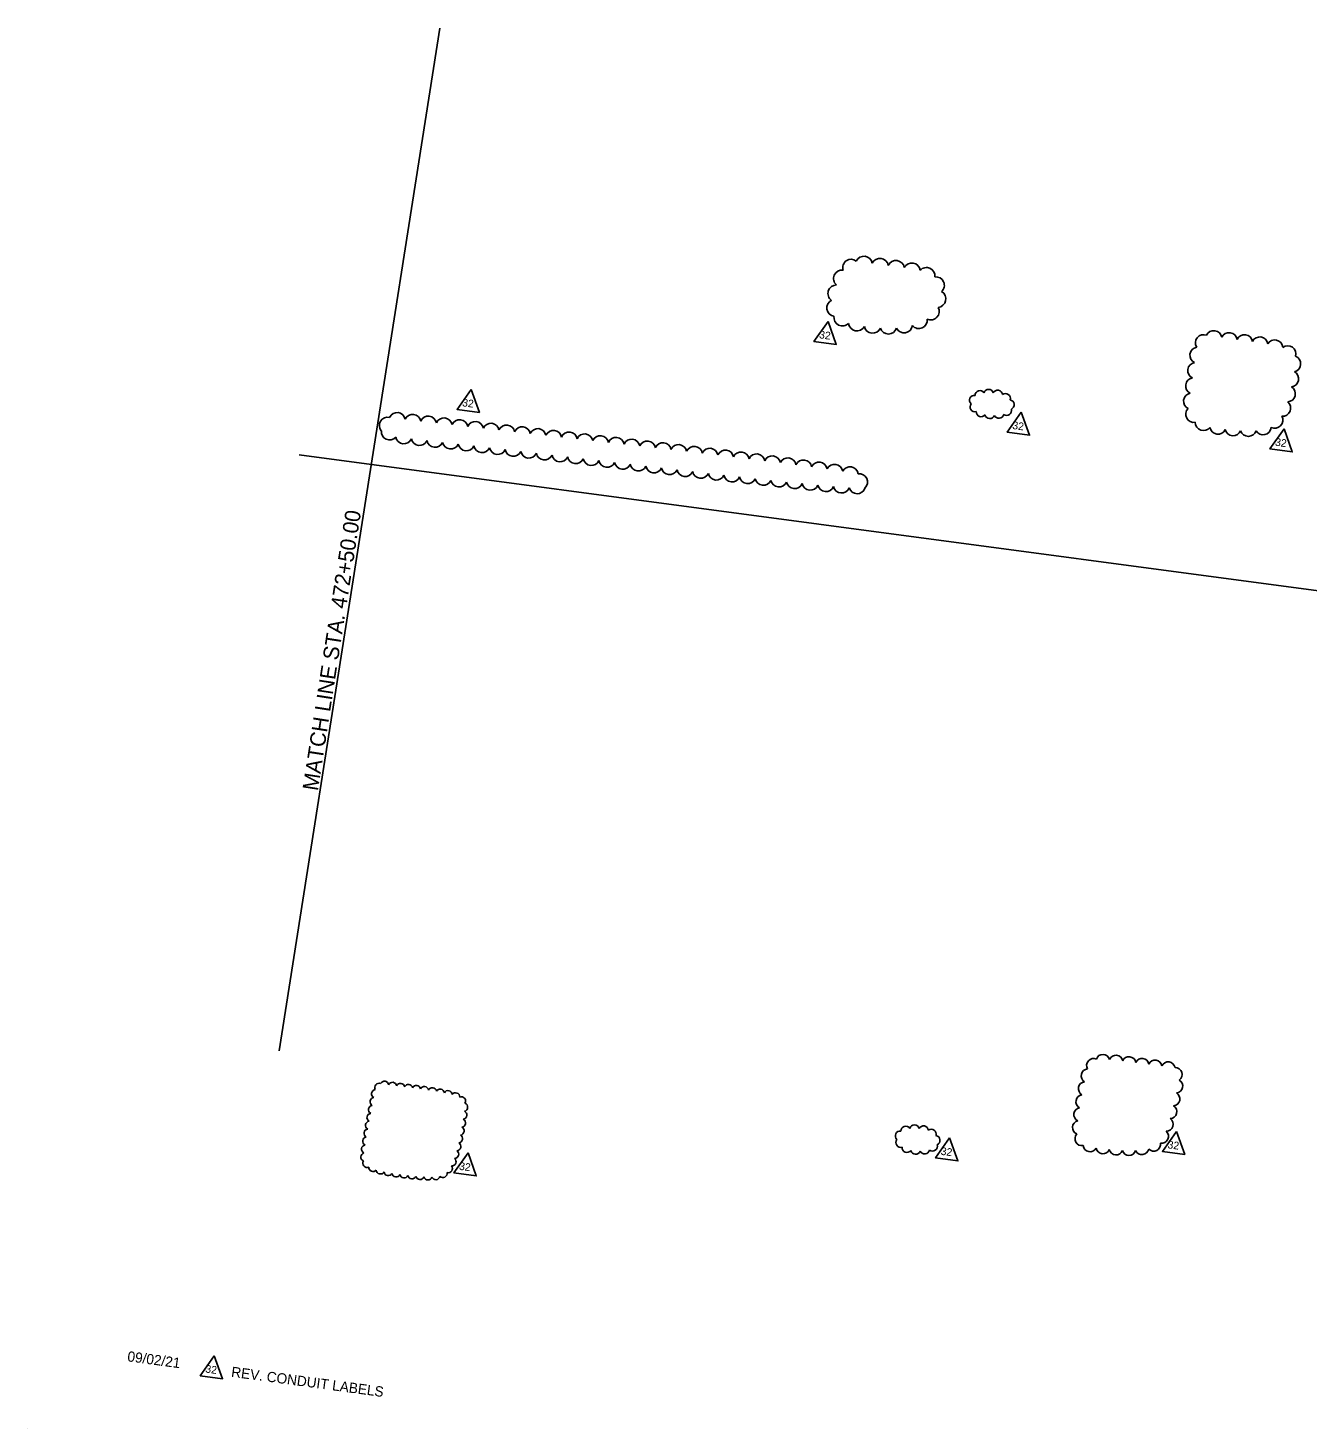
# Model space of a CAD drawing. Extents: x 925493 to 926837, y 636307 to 637171.
# Drawn here: x 925493 to 926150, y 636452 to 637171 of the extents above; entities that cross this region are included whole.
import ezdxf

# ---------------------------------------------------------------- set-up
doc = ezdxf.new("R2010")
doc.units = 0
for name, color, linetype in [('ActivePointCell_dp', 7, 'Continuous'), ('AdhocPoint_dp', 7, 'Continuous'), ('Cloud_dp', 7, 'Continuous'), ('MatchLines_dp', 7, 'Continuous'), ('TextLabel', 7, 'Continuous'), ('TextNotes', 7, 'Continuous')]:
    doc.layers.add(name, color=color, linetype=linetype)

msp = doc.modelspace()

# ---------------------------------------------------------------- linework, layer by layer
at = {"layer": 'ActivePointCell_dp'}
msp.add_line((926709.43, 636807.88), (925632.34, 636951.66), dxfattribs=at)
at = {"layer": 'AdhocPoint_dp'}
msp.add_line((925493.14, 636452.35), (925493.14, 636452.35), dxfattribs=at)
at = {"layer": 'Cloud_dp'}
for points in [[(925903.7, 637020.16), (925896.5, 637009.89), (925907.95, 637008.36)], [(925720.53, 636985.27), (925713.33, 636975.01), (925724.78, 636973.48)], [(926002.88, 636973.59), (925995.68, 636963.33), (926007.13, 636961.8)], [(926137.71, 636965), (926130.51, 636954.74), (926141.96, 636953.21)], [(925966.12, 636601.18), (925958.92, 636590.92), (925970.38, 636589.39)], [(926082.55, 636604.53), (926075.35, 636594.26), (926086.81, 636592.74)], [(925718.95, 636593.49), (925711.75, 636583.23), (925723.2, 636581.7)]]:
    msp.add_lwpolyline(points, close=True, dxfattribs=at)
for centre, radius, start, end in [((925915.56, 637047.7), 4.34, 52.01002, 197.01002), ((925922.15, 637049.28), 4.34, 9.89674, 154.89674), ((925930.36, 637048.19), 4.34, 9.89674, 154.89674), ((925938.56, 637047.09), 4.34, 9.80382, 154.80382), ((925910.88, 637042.13), 4.34, 83.06239, 228.06239), ((925946.68, 637045.82), 4.34, 7.52021, 152.52021), ((925954.22, 637043.5), 4.34, 353.21175, 138.21175), ((925908.01, 637034.56), 4.34, 90.39209, 235.39209), ((925959.07, 637038.68), 4.34, 312.15567, 97.15567), ((925907.45, 637027.09), 4.34, 116.00337, 261.00337), ((925959.83, 637031.7), 4.34, 275.24637, 60.24637), ((925911.06, 637022.17), 4.34, 171.5858, 316.5858), ((925956.45, 637025.24), 4.34, 244.59572, 29.59572), ((925918.53, 637019.67), 4.34, 186.41343, 331.41343), ((925926.59, 637018.47), 4.34, 191.6571, 336.6571), ((925934.72, 637018.02), 4.34, 196.9198, 341.9198), ((925942.72, 637018.62), 4.34, 206.67781, 351.67781), ((925950.28, 637020.85), 4.34, 221.20066, 6.20066), ((926101.69, 637011.29), 4.16, 9.89674, 154.89674), ((926109.56, 637010.24), 4.16, 9.89674, 154.89674), ((926096.37, 637009.19), 4.16, 68.20431, 213.20431), ((926117.43, 637009.19), 4.16, 9.89674, 154.89674), ((926125.26, 637008.07), 4.16, 8.77387, 153.77387), ((926132.95, 637006.57), 4.16, 4.20701, 149.20701), ((926139.62, 637003.56), 4.16, 342.21927, 127.21927), ((926093.58, 637002.81), 4.16, 99.5249, 244.5249), ((926142.07, 636998.41), 4.16, 283.66055, 68.66055), ((926092.48, 636994.95), 4.16, 99.54688, 244.54688), ((926141.07, 636990.71), 4.16, 276.46775, 61.46775), ((926091.39, 636987.09), 4.16, 99.62003, 244.62003), ((926139.37, 636983.03), 4.16, 273.58469, 58.58469), ((925978.82, 636979.74), 2.51, 82.67056, 227.67056), ((925981.65, 636982.19), 2.51, 34.10765, 179.10765), ((925986.12, 636982.81), 2.51, 16.71694, 161.71694), ((925990.75, 636982.35), 2.51, 6.96113, 151.96113), ((925994.79, 636980.67), 2.51, 342.91745, 127.91745), ((925996.74, 636977.46), 2.51, 294.76198, 79.76198), ((926090.31, 636979.22), 4.16, 99.75917, 244.75917), ((926136.95, 636975.68), 4.16, 264.96518, 49.96518), ((925682.55, 636969.18), 4.23, 10.80208, 155.80208), ((925690.58, 636968.25), 4.23, 10.95178, 155.95178), ((925698.6, 636967.33), 4.23, 10.98257, 155.98257), ((925979.09, 636976.31), 2.51, 141.30835, 286.30835), ((925982.3, 636973.75), 2.51, 176.73132, 321.73132), ((925986.71, 636972.83), 2.51, 194.62704, 339.62704), ((925991.37, 636972.97), 2.52, 203.8708, 348.8708), ((925995.39, 636974.46), 2.51, 231.69605, 16.69605), ((926091.46, 636972.5), 4.16, 134.77757, 279.77757), ((926132.95, 636969.5), 4.16, 244.31058, 29.31058), ((925677.66, 636966.81), 4.23, 75.9759, 220.9759), ((925706.62, 636966.42), 4.23, 10.9986, 155.9986), ((925714.65, 636965.5), 4.23, 11.00888, 156.00888), ((925722.67, 636964.59), 4.23, 11.01618, 156.01618), ((925730.7, 636963.68), 4.23, 11.02173, 156.02173), ((925738.72, 636962.77), 4.23, 11.02612, 156.02612), ((925746.75, 636961.86), 4.23, 11.02971, 156.02971), ((925754.77, 636960.95), 4.23, 11.03272, 156.03272), ((925762.79, 636960.04), 4.23, 11.03528, 156.03528), ((926096.33, 636968.28), 4.16, 178.33859, 323.33859), ((926103.78, 636966.48), 4.16, 189.46094, 334.46094), ((926111.59, 636965.62), 4.16, 192.99146, 337.99146), ((926127.01, 636966.14), 4.16, 209.59075, 354.59075), ((925678.68, 636963.56), 4.23, 173.62719, 318.62719), ((925686, 636961.6), 4.23, 191.40074, 336.40074), ((925694.04, 636960.73), 4.23, 191.17285, 336.17285), ((925702.06, 636959.83), 4.23, 191.05511, 336.05511), ((925710.09, 636958.92), 4.23, 190.97993, 335.97993), ((925718.11, 636958), 4.23, 190.92656, 335.92656), ((925770.82, 636959.13), 4.23, 11.03751, 156.03751), ((925778.84, 636958.22), 4.23, 11.03946, 156.03946), ((925786.87, 636957.31), 4.23, 11.04119, 156.04119), ((925794.89, 636956.4), 4.23, 11.04274, 156.04274), ((925802.92, 636955.49), 4.23, 11.04408, 156.04408), ((925810.94, 636954.58), 4.23, 11.01548, 156.01548), ((925818.96, 636953.67), 4.23, 10.95791, 155.95791), ((925826.98, 636952.74), 4.23, 10.89381, 155.89381), ((926119.41, 636965.33), 4.16, 197.6746, 342.6746), ((925726.14, 636957.07), 4.23, 190.88612, 335.88612), ((925734.16, 636956.14), 4.23, 190.85412, 335.85412), ((925742.18, 636955.2), 4.23, 190.82797, 335.82797), ((925750.2, 636954.26), 4.23, 190.80609, 335.80609), ((925758.22, 636953.32), 4.23, 190.78741, 335.78741), ((925766.24, 636952.37), 4.23, 190.77124, 335.77124), ((925774.26, 636951.42), 4.23, 190.75705, 335.75705), ((925835, 636951.81), 4.23, 10.82186, 155.82186), ((925843.02, 636950.87), 4.23, 10.74032, 155.74032), ((925851.04, 636949.91), 4.23, 10.64682, 155.64682), ((925859.05, 636948.94), 4.23, 10.53815, 155.53815), ((925867.07, 636947.95), 4.23, 10.40969, 155.40969), ((925875.07, 636946.94), 4.23, 10.25458, 155.25458), ((925883.08, 636945.91), 4.23, 10.0621, 155.0621), ((925782.28, 636950.48), 4.23, 190.74447, 335.74447), ((925790.3, 636949.52), 4.23, 190.73477, 335.73477), ((925798.32, 636948.57), 4.23, 190.7552, 335.7552), ((925806.34, 636947.63), 4.23, 190.78932, 335.78932), ((925814.36, 636946.69), 4.23, 190.82718, 335.82718), ((925822.38, 636945.75), 4.23, 190.86951, 335.86951), ((925830.4, 636944.82), 4.23, 190.91729, 335.91729), ((925838.43, 636943.9), 4.23, 190.97179, 335.97179), ((925891.08, 636944.85), 4.23, 9.81432, 154.81432), ((925899.07, 636943.75), 4.23, 9.47827, 154.47827), ((925907.05, 636942.59), 4.23, 8.98444, 153.98444), ((925915.01, 636941.34), 4.23, 8.14869, 153.14869), ((925846.45, 636942.99), 4.23, 191.03473, 336.03473), ((925854.47, 636942.08), 4.23, 191.10857, 336.10857), ((925862.5, 636941.19), 4.23, 191.19687, 336.19687), ((925870.52, 636940.31), 4.23, 191.30506, 336.30506), ((925878.55, 636939.45), 4.23, 191.44197, 336.44197), ((925886.58, 636938.61), 4.23, 191.62312, 336.62312), ((925894.6, 636937.8), 4.23, 191.87914, 336.87914), ((925902.64, 636937.04), 4.23, 192.28253, 337.28253), ((925910.67, 636936.36), 4.23, 193.07403, 338.07403), ((925919.79, 636937.76), 4.22, 313.01562, 98.01562), ((925918.65, 636936), 4.24, 196.68432, 341.68432), ((926039.96, 636638.4), 3.55, 65.89656, 210.89656), ((926044.78, 636640.51), 3.55, 16.33707, 161.33707), ((926051.45, 636640.11), 3.55, 11.8731, 156.8731), ((926058.15, 636639.35), 3.55, 10.18551, 155.18551), ((926064.85, 636638.47), 3.55, 9.89674, 154.89674), ((926071.57, 636637.58), 3.55, 9.89674, 154.89674), ((926037.16, 636633.04), 3.55, 93.9727, 238.9727), ((926078.28, 636636.68), 3.55, 9.89674, 154.89674), ((926081.85, 636633.74), 3.55, 306.25893, 91.25893), ((925673.24, 636627.09), 2.16, 65.85108, 210.85108), ((925676.08, 636628.14), 2.16, 9.89674, 154.89674), ((925680.18, 636627.6), 2.16, 9.89674, 154.89674), ((925684.27, 636627.05), 2.16, 9.89674, 154.89674), ((925688.36, 636626.5), 2.16, 9.89674, 154.89674), ((925692.45, 636625.96), 2.16, 9.89674, 154.89674), ((925696.54, 636625.41), 2.16, 9.75068, 154.75068), ((925700.62, 636624.81), 2.16, 8.73461, 153.73461), ((926035.72, 636626.47), 3.55, 96.25509, 241.25509), ((926082.19, 636627.8), 3.55, 275.16985, 60.16985), ((925670.83, 636619.77), 2.16, 96.45129, 241.45129), ((925671.63, 636623.83), 2.17, 96.45129, 241.45129), ((925704.67, 636624.13), 2.16, 7.13442, 152.13442), ((925708.68, 636623.3), 2.16, 4.51888, 149.51888), ((925712.59, 636622.2), 2.16, 358.98635, 143.98635), ((925715.58, 636620.16), 2.16, 327.49222, 112.49222), ((926034.47, 636619.84), 3.55, 97.42522, 242.42522), ((926080.73, 636621.19), 3.55, 274.9437, 59.9437), ((925669.25, 636611.67), 2.16, 96.49297, 241.49297), ((925670.04, 636615.72), 2.16, 96.45129, 241.45129), ((925716.19, 636612.93), 2.16, 279.27811, 64.27811), ((925716.62, 636616.98), 2.16, 283.68875, 68.68875), ((926033.41, 636613.19), 3.55, 99.3757, 244.3757), ((926079.16, 636614.64), 3.55, 273.1814, 58.1814), ((925667.74, 636603.56), 2.16, 97.47942, 242.47942), ((925668.48, 636607.62), 2.16, 96.8773, 241.8773), ((925714.8, 636604.83), 2.16, 276.53856, 61.53856), ((925715.55, 636608.87), 2.16, 277.54102, 62.54102), ((925943.58, 636604.7), 2.51, 34.10765, 179.10765), ((925948.05, 636605.33), 2.51, 16.71694, 161.71694), ((925952.68, 636604.87), 2.51, 6.96113, 151.96113), ((925956.72, 636603.19), 2.51, 342.91745, 127.91745), ((926032.71, 636606.54), 3.55, 103.70817, 248.70817), ((926077.32, 636608.19), 3.55, 269.89528, 54.89528), ((925667.06, 636599.5), 2.16, 98.38284, 243.38284), ((925713.09, 636596.78), 2.16, 273.85634, 58.85634), ((925713.99, 636600.79), 2.16, 275.78706, 60.78706), ((925940.75, 636602.25), 2.51, 82.67056, 227.67056), ((925941.02, 636598.82), 2.51, 141.30835, 286.30835), ((925958.67, 636599.98), 2.51, 294.76198, 79.76198), ((926033.98, 636600.76), 3.55, 136.04735, 281.04735), ((926070.82, 636597.99), 3.55, 224.22548, 9.22548), ((926074.86, 636602.07), 3.55, 261.3019, 46.3019), ((925666.08, 636591.38), 2.16, 104.26865, 249.26865), ((925666.46, 636595.44), 2.16, 99.97464, 244.97464), ((925710.65, 636589), 2.16, 265.28782, 50.28782), ((925712.01, 636592.83), 2.16, 270.60913, 55.60913), ((925944.23, 636596.26), 2.51, 176.73132, 321.73132), ((925948.64, 636595.34), 2.51, 194.62704, 339.62704), ((925953.3, 636595.48), 2.52, 203.8708, 348.8708), ((925957.32, 636596.97), 2.51, 231.69605, 16.69605), ((926038.19, 636597.64), 3.55, 185.84552, 330.84552), ((926044.77, 636596.61), 3.55, 191.40516, 336.40516), ((926051.48, 636596.03), 3.55, 193.62514, 338.62514), ((926058.18, 636595.78), 3.55, 197.11492, 342.11492), ((926064.78, 636596.16), 3.55, 204.51065, 349.51065), ((925667.15, 636588.22), 2.17, 148.30199, 293.30199), ((925670.17, 636586.08), 2.16, 176.00616, 321.00616), ((925674.01, 636584.85), 2.16, 183.47027, 328.47027), ((925678.01, 636583.98), 2.16, 187.15865, 332.15865), ((925706.09, 636582.99), 2.16, 225.45089, 10.45089), ((925708.8, 636585.47), 2.16, 254.50213, 39.50213), ((925682.06, 636583.33), 2.16, 189.41457, 334.41457), ((925686.14, 636582.79), 2.16, 190.60994, 335.60994), ((925690.23, 636582.34), 2.16, 191.81586, 336.81586), ((925694.32, 636581.99), 2.16, 193.54834, 338.54834), ((925698.41, 636581.81), 2.16, 196.34653, 341.34653), ((925702.47, 636581.93), 2.16, 202.07619, 347.07619)]:
    msp.add_arc(centre, radius, start, end, dxfattribs=at)
at = {"layer": 'MatchLines_dp'}
msp.add_line((925704.52, 637170.73), (925622.06, 636645.93), dxfattribs=at)
at = {"layer": 'TextNotes'}
msp.add_lwpolyline([(925588.74, 636489.44), (925581.54, 636479.18), (925592.99, 636477.65)], close=True, dxfattribs=at)

# ---------------------------------------------------------------- texts
at = {"layer": 'Cloud_dp'}
for p in [(925898.96, 637011.56), (925715.79, 636976.68), (925998.14, 636965), (926132.97, 636956.41), (926077.81, 636595.93), (925961.38, 636592.58), (925714.21, 636584.89)]:
    msp.add_text('32', height=3.938, rotation=352.39674, dxfattribs=at).set_placement(p)
at = {"layer": 'MatchLines_dp'}
msp.add_text('MATCH LINE STA. 472+50.00', height=8, rotation=81.19875, dxfattribs=at).set_placement((925641.88, 636778.99))
at = {"layer": 'TextLabel'}
for s, p in [('09/02/21', (925543.91, 636486.63)), ('REV. CONDUIT LABELS', (925597.2, 636478.67))]:
    msp.add_text(s, height=5.25, rotation=352.39674, dxfattribs=at).set_placement(p)
at = {"layer": 'TextNotes'}
msp.add_text('32', height=3.938, rotation=352.39674, dxfattribs=at).set_placement((925584, 636480.85))

doc.saveas('drawing.dxf')
